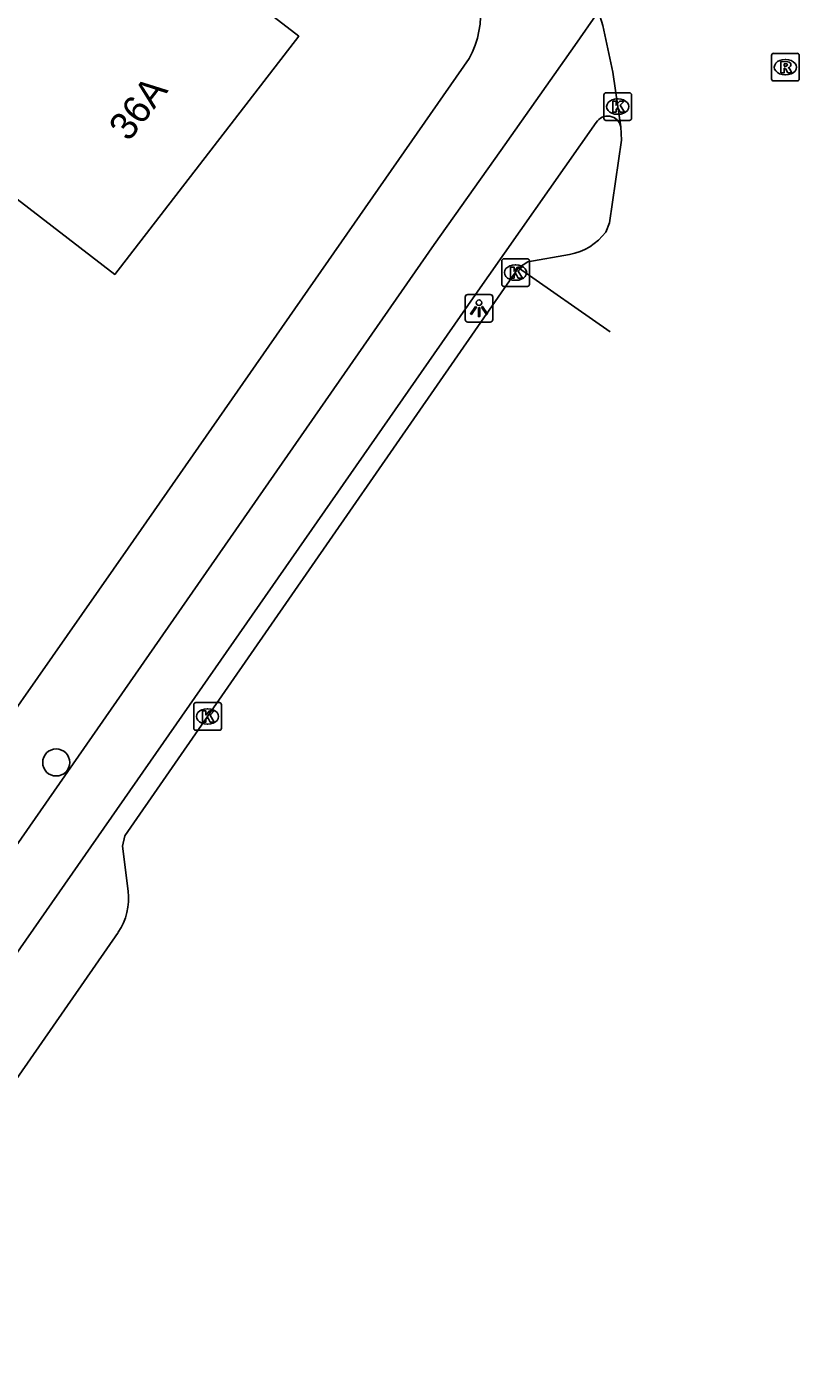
# Model space of a CAD drawing. Extents: x 160158 to 160921, y 381517 to 382041.
# Drawn here: x 160637.39 to 160665.35, y 381577.96 to 381626.43 of the extents above; entities that cross this region are included whole.
import ezdxf

# ---------------------------------------------------------------- set-up
doc = ezdxf.new("R2010")
doc.units = 0
for name, color, linetype in [('IMGEO_Boom', 7, 'Continuous'), ('IMGEO_Fietspad_open', 7, 'Continuous'), ('IMGEO_Kolk', 7, 'Continuous'), ('IMGEO_Lichtpunt', 7, 'Continuous'), ('IMGEO_Pand', 7, 'Continuous'), ('IMGEO_Pand_nummerreeks', 7, 'Continuous'), ('IMGEO_Rijbaan_lokaal_gesloten', 7, 'Continuous'), ('IMGEO_Rijbaan_lokaal_open', 7, 'Continuous'), ('IMGEO_Rioolput', 7, 'Continuous'), ('IMGEO_Voetpad_open', 7, 'Continuous')]:
    doc.layers.add(name, color=color, linetype=linetype)

msp = doc.modelspace()

# ---------------------------------------------------------------- linework, layer by layer
at = {"layer": 'IMGEO_Boom'}
msp.add_circle((160638.457, 381599.805), 0.489, dxfattribs=at)
at = {"layer": 'IMGEO_Fietspad_open'}
for points in [[(160658.078, 381626.982), (160657.224, 381625.75), (160654.545, 381621.952), (160652.131, 381618.546), (160625.5, 381580.252)], [(160626.609, 381577.958), (160653.548, 381616.624), (160658.001, 381622.958)]]:
    msp.add_lwpolyline(points, dxfattribs=at)
msp.add_arc((160658.417, 381622.716), 0.481, 10.9473, 149.7516, dxfattribs=at)
at = {"layer": 'IMGEO_Kolk'}
for p, q in [((160658.278, 381623.113), (160658.278, 381623.965)), ((160658.353, 381624.039), (160659.205, 381624.039)), ((160659.279, 381623.965), (160659.279, 381623.113)), ((160658.766, 381623.819), (160658.791, 381623.819)), ((160659.205, 381623.039), (160658.353, 381623.039)), ((160658.789, 381623.259), (160658.764, 381623.259)), ((160654.582, 381617.106), (160654.582, 381617.958)), ((160654.657, 381618.032), (160655.509, 381618.032)), ((160655.07, 381617.812), (160655.095, 381617.812)), ((160655.583, 381617.958), (160655.583, 381617.106)), ((160655.093, 381617.252), (160655.068, 381617.252)), ((160655.509, 381617.032), (160654.657, 381617.032)), ((160643.434, 381601.043), (160643.434, 381601.895)), ((160643.509, 381601.969), (160644.361, 381601.969)), ((160643.922, 381601.749), (160643.947, 381601.749)), ((160644.435, 381601.895), (160644.435, 381601.043)), ((160643.945, 381601.189), (160643.92, 381601.189)), ((160644.361, 381600.969), (160643.509, 381600.969))]:
    msp.add_line(p, q, dxfattribs=at)
for points in [[(160658.278, 381623.113), (160658.278, 381623.965)], [(160658.353, 381624.039), (160659.205, 381624.039)], [(160659.279, 381623.965), (160659.279, 381623.113)], [(160658.599, 381623.739), (160658.722, 381623.739), (160658.722, 381623.588), (160658.852, 381623.739), (160659.016, 381623.739), (160658.87, 381623.588), (160659.023, 381623.339), (160658.871, 381623.339), (160658.786, 381623.503), (160658.722, 381623.436), (160658.722, 381623.339), (160658.599, 381623.339), (160658.599, 381623.739)], [(160659.205, 381623.039), (160658.353, 381623.039)], [(160654.582, 381617.106), (160654.582, 381617.958)], [(160654.657, 381618.032), (160655.509, 381618.032)], [(160654.903, 381617.732), (160655.026, 381617.732), (160655.026, 381617.581), (160655.156, 381617.732), (160655.32, 381617.732), (160655.174, 381617.581), (160655.327, 381617.332), (160655.175, 381617.332), (160655.09, 381617.496), (160655.026, 381617.429), (160655.026, 381617.332), (160654.903, 381617.332), (160654.903, 381617.732)], [(160655.583, 381617.958), (160655.583, 381617.106)], [(160655.509, 381617.032), (160654.657, 381617.032)], [(160643.434, 381601.043), (160643.434, 381601.895)], [(160643.509, 381601.969), (160644.361, 381601.969)], [(160643.755, 381601.669), (160643.878, 381601.669), (160643.878, 381601.518), (160644.008, 381601.669), (160644.172, 381601.669), (160644.026, 381601.518), (160644.179, 381601.269), (160644.027, 381601.269), (160643.942, 381601.433), (160643.878, 381601.366), (160643.878, 381601.269), (160643.755, 381601.269), (160643.755, 381601.669)], [(160644.435, 381601.895), (160644.435, 381601.043)], [(160644.361, 381600.969), (160643.509, 381600.969)]]:
    msp.add_lwpolyline(points, dxfattribs=at)
for centre, start, end in [((160658.355, 381623.963), 91.552, 178.448), ((160658.355, 381623.963), 91.552, 178.448), ((160659.203, 381623.963), 1.552, 88.448), ((160659.203, 381623.963), 1.552, 88.448), ((160658.355, 381623.115), 181.552, 268.448), ((160658.355, 381623.115), 181.552, 268.448), ((160659.203, 381623.115), 271.552, 358.448), ((160659.203, 381623.115), 271.552, 358.448), ((160654.659, 381617.956), 91.552, 178.448), ((160654.659, 381617.956), 91.552, 178.448), ((160655.507, 381617.956), 1.552, 88.448), ((160655.507, 381617.956), 1.552, 88.448), ((160654.659, 381617.108), 181.552, 268.448), ((160654.659, 381617.108), 181.552, 268.448), ((160655.507, 381617.108), 271.552, 358.448), ((160655.507, 381617.108), 271.552, 358.448), ((160643.511, 381601.893), 91.552, 178.448), ((160643.511, 381601.893), 91.552, 178.448), ((160644.359, 381601.893), 1.552, 88.448), ((160644.359, 381601.893), 1.552, 88.448), ((160643.511, 381601.045), 181.552, 268.448), ((160643.511, 381601.045), 181.552, 268.448), ((160644.359, 381601.045), 271.552, 358.448), ((160644.359, 381601.045), 271.552, 358.448)]:
    msp.add_arc(centre, 0.0765, start, end, dxfattribs=at)
for centre, major_axis, ratio, start_param, end_param in [((160658.765, 381623.539), (-0.387, 0.002), 0.722429, 4.712389, 7.853982), ((160658.79, 381623.539), (-0.39, 0.002), 0.717154, 1.570796, 4.712389), ((160655.069, 381617.532), (-0.387, 0.002), 0.722429, 4.712389, 7.853982), ((160655.094, 381617.532), (-0.39, 0.002), 0.717154, 1.570796, 4.712389), ((160643.921, 381601.469), (-0.387, 0.002), 0.722429, 4.712389, 7.853982), ((160643.946, 381601.469), (-0.39, 0.002), 0.717154, 1.570796, 4.712389)]:
    msp.add_ellipse(centre, major_axis=major_axis, ratio=ratio, start_param=start_param, end_param=end_param, dxfattribs=at)
at = {"layer": 'IMGEO_Lichtpunt'}
for p, q in [((160654.162, 381616.738), (160653.354, 381616.738)), ((160654.162, 381616.738), (160653.354, 381616.738)), ((160653.26, 381616.643), (160653.26, 381615.836)), ((160653.26, 381616.643), (160653.26, 381615.836)), ((160654.256, 381615.836), (160654.256, 381616.643)), ((160654.256, 381615.836), (160654.256, 381616.643)), ((160653.354, 381615.742), (160654.162, 381615.742)), ((160653.354, 381615.742), (160654.162, 381615.742))]:
    msp.add_line(p, q, dxfattribs=at)
for points in [[(160653.634, 381616.307), (160653.673, 381616.279), (160653.485, 381616.017), (160653.447, 381616.044), (160653.634, 381616.307)], [(160653.736, 381616.259), (160653.783, 381616.259), (160653.783, 381615.937), (160653.736, 381615.937), (160653.736, 381616.259)], [(160653.846, 381616.279), (160653.884, 381616.306), (160654.071, 381616.044), (160654.032, 381616.016), (160653.846, 381616.279)]]:
    msp.add_lwpolyline(points, dxfattribs=at)
msp.add_circle((160653.759, 381616.441), 0.0994, dxfattribs=at)
for centre, start, end in [((160653.354, 381616.643), 90, 180), ((160653.354, 381616.643), 90, 180), ((160654.162, 381616.643), 0, 90), ((160654.162, 381616.643), 0, 90), ((160653.354, 381615.836), 180, 270), ((160653.354, 381615.836), 180, 270), ((160654.162, 381615.836), 270, 0), ((160654.162, 381615.836), 270, 360)]:
    msp.add_arc(centre, 0.0946, start, end, dxfattribs=at)
at = {"layer": 'IMGEO_Pand'}
msp.add_lwpolyline([(160636.053, 381630.085), (160631.637, 381624.368), (160636.619, 381620.52), (160640.576, 381617.464), (160647.232, 381626.081), (160639.436, 381632.103)], dxfattribs=at)
at = {"layer": 'IMGEO_Rijbaan_lokaal_gesloten'}
for points in [[(160655.189, 381617.701), (160643.936, 381601.467), (160640.935, 381597.149), (160640.855, 381596.771), (160641.058, 381595.153)], [(160658.503, 381615.393), (160655.189, 381617.701)], [(160640.703, 381593.658), (160634.753, 381585.096)]]:
    msp.add_lwpolyline(points, dxfattribs=at)
msp.add_arc((160638.854, 381594.887), 2.22, 326.3968, 6.8873, dxfattribs=at)
at = {"layer": 'IMGEO_Rijbaan_lokaal_open'}
for points in [[(160658.078, 381626.982), (160658.246, 381626.478), (160658.598, 381624.784), (160658.778, 381623.539), (160658.889, 381622.807)], [(160658.889, 381622.807), (160658.911, 381622.32), (160658.483, 381619.337), (160658.345, 381619)], [(160657.032, 381618.184), (160655.53, 381617.923), (160655.189, 381617.701)]]:
    msp.add_lwpolyline(points, dxfattribs=at)
msp.add_arc((160656.655, 381620.255), 2.105, 280.3134, 323.4067, dxfattribs=at)
at = {"layer": 'IMGEO_Rioolput'}
for p, q in [((160664.421, 381625.465), (160665.273, 381625.465)), ((160664.346, 381624.539), (160664.346, 381625.391)), ((160664.834, 381625.245), (160664.859, 381625.245)), ((160665.347, 381625.391), (160665.347, 381624.539)), ((160665.273, 381624.465), (160664.421, 381624.465)), ((160664.857, 381624.685), (160664.832, 381624.685))]:
    msp.add_line(p, q, dxfattribs=at)
for points in [[(160664.421, 381625.465), (160665.273, 381625.465)], [(160664.346, 381624.539), (160664.346, 381625.391)], [(160664.935, 381625.163), (160664.683, 381625.165), (160664.683, 381624.765)], [(160664.683, 381624.765), (160664.807, 381624.765), (160664.807, 381624.927), (160664.818, 381624.927)], [(160664.861, 381625.084), (160664.807, 381625.084), (160664.807, 381625.003)], [(160664.807, 381625.003), (160664.859, 381625.003)], [(160665.347, 381625.391), (160665.347, 381624.539)], [(160665.273, 381624.465), (160664.421, 381624.465)], [(160664.865, 381624.898), (160664.936, 381624.765), (160665.076, 381624.765), (160665.011, 381624.891)]]:
    msp.add_lwpolyline(points, dxfattribs=at)
for centre, radius, start, end in [((160664.423, 381625.389), 0.0765, 91.552, 178.448), ((160664.423, 381625.389), 0.0765, 91.552, 178.448), ((160665.271, 381625.389), 0.0765, 1.552, 88.448), ((160665.271, 381625.389), 0.0765, 1.552, 88.448), ((160664.817, 381624.874), 0.0533, 26.0293, 88.6989), ((160664.843, 381625.192), 0.19, 274.7715, 282.9687), ((160664.867, 381624.988), 0.0964, 77.0061, 93.1865), ((160664.881, 381625.045), 0.0378, 276.6634, 79.6772), ((160664.934, 381625.053), 0.109, 350.3612, 89.416), ((160664.932, 381625.053), 0.112, 277.5842, 350.9817), ((160664.916, 381624.838), 0.108, 29.5134, 73.7905), ((160664.423, 381624.541), 0.0765, 181.552, 268.448), ((160664.423, 381624.541), 0.0765, 181.552, 268.448), ((160665.271, 381624.541), 0.0765, 271.552, 358.448), ((160665.271, 381624.541), 0.0765, 271.552, 358.448)]:
    msp.add_arc(centre, radius, start, end, dxfattribs=at)
for centre, major_axis, ratio, start_param, end_param in [((160664.833, 381624.965), (-0.387, 0.002), 0.722429, 4.712389, 7.853982), ((160664.858, 381624.965), (-0.39, 0.002), 0.717154, 1.570796, 4.712389)]:
    msp.add_ellipse(centre, major_axis=major_axis, ratio=ratio, start_param=start_param, end_param=end_param, dxfattribs=at)
at = {"layer": 'IMGEO_Voetpad_open'}
msp.add_lwpolyline([(160633.366, 381596.557), (160641.062, 381607.564), (160653.405, 381625.283)], dxfattribs=at)
msp.add_arc((160650.462, 381626.89), 3.353, 331.3676, 42.3752, dxfattribs=at)

# ---------------------------------------------------------------- texts
at = {"layer": 'IMGEO_Pand_nummerreeks'}
msp.add_text('36A', height=1, rotation=52.3165, dxfattribs=at).set_placement((160641.081, 381622.239))

doc.saveas('drawing.dxf')
